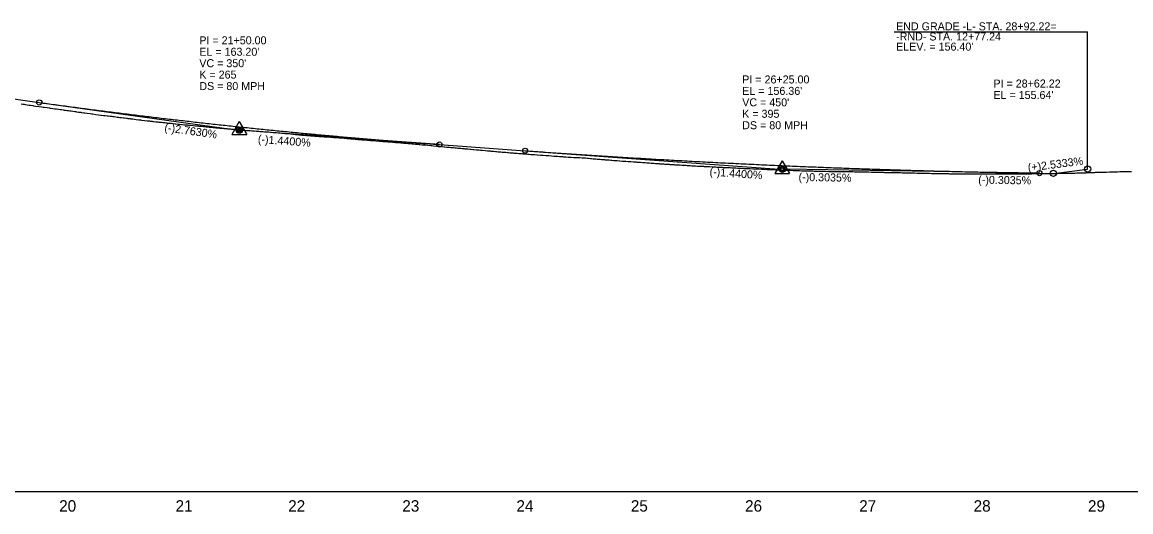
# Model space of a CAD drawing. Extents: x 1778432 to 1784301, y 601022 to 621789.
# Drawn here: x 1781103 to 1782073, y 621022 to 621450 of the extents above; entities that cross this region are included whole.
import ezdxf

# ---------------------------------------------------------------- set-up
doc = ezdxf.new("R2010")
doc.units = 0
for name, color, linetype in [('Exist Profile Cell', 7, 'Continuous'), ('Exist Vertical Profile Ground Line', 7, 'Continuous'), ('Exist Vertical Profile Horizontal Axis Label Major', 7, 'Continuous'), ('Prop PFL VPI Symbol CELL', 7, 'Continuous'), ('Prop Vertical Profile Curve Label', 7, 'Continuous'), ('Prop Vertical Profile Grade', 7, 'Continuous'), ('Prop Vertical Profile Grade Label', 7, 'Continuous'), ('Prop VPI Label', 7, 'Continuous')]:
    doc.layers.add(name, color=color, linetype=linetype)

msp = doc.modelspace()

# ---------------------------------------------------------------- linework, layer by layer
at = {"layer": 'Exist Profile Cell'}
msp.add_line((1780142.96, 621039.19), (1784155.69, 621039.19), dxfattribs=at)
at = {"layer": 'Exist Vertical Profile Ground Line'}
msp.add_lwpolyline([(1781102.23, 621378.18), (1781103.68, 621377.98), (1781104.73, 621377.81), (1781105.67, 621377.66), (1781107.23, 621377.43), (1781109.02, 621377.12), (1781109.74, 621377), (1781110.39, 621376.89), (1781112.24, 621376.6), (1781112.76, 621376.52), (1781114.75, 621376.24), (1781117.49, 621375.88), (1781119.75, 621375.55), (1781121.39, 621375.35), (1781122.26, 621375.24), (1781124.77, 621374.88), (1781126.96, 621374.56), (1781127.27, 621374.52), (1781127.62, 621374.47), (1781129.78, 621374.15), (1781131.68, 621373.87), (1781132.28, 621373.79), (1781132.96, 621373.7), (1781134.78, 621373.45), (1781136.4, 621373.22), (1781137.29, 621373.11), (1781138.78, 621372.9), (1781139.79, 621372.77), (1781140.95, 621372.61), (1781142.3, 621372.4), (1781143.5, 621372.23), (1781144.8, 621372.06), (1781145.87, 621371.91), (1781147.31, 621371.71), (1781148.93, 621371.51), (1781149.81, 621371.37), (1781150.59, 621371.26), (1781152.32, 621371.01), (1781154.25, 621370.75), (1781154.82, 621370.66), (1781156.92, 621370.35), (1781157.32, 621370.29), (1781157.69, 621370.24), (1781159.83, 621369.95), (1781162.33, 621369.63), (1781163.83, 621369.43), (1781164.84, 621369.29), (1781167.55, 621368.91), (1781169.84, 621368.64), (1781171.87, 621368.39), (1781172.35, 621368.33), (1781174.26, 621368.07), (1781174.86, 621368), (1781175.53, 621367.91), (1781177.36, 621367.69), (1781178.21, 621367.6), (1781179.86, 621367.4), (1781181.34, 621367.26), (1781182.37, 621367.14), (1781183.52, 621367), (1781184.87, 621366.81), (1781186.19, 621366.64), (1781187.37, 621366.49), (1781188.43, 621366.35), (1781189.88, 621366.18), (1781191.5, 621365.97), (1781192.38, 621365.86), (1781194.18, 621365.62), (1781194.89, 621365.52), (1781195.52, 621365.44), (1781197.39, 621365.24), (1781197.9, 621365.18), (1781199.89, 621364.92), (1781202.61, 621364.59), (1781204.99, 621364.32), (1781206.51, 621364.13), (1781207.46, 621364), (1781210.14, 621363.67), (1781212.42, 621363.41), (1781214.45, 621363.18), (1781214.93, 621363.13), (1781216.81, 621362.9), (1781217.43, 621362.83), (1781218.12, 621362.75), (1781219.93, 621362.54), (1781221.54, 621362.36), (1781222.44, 621362.27), (1781223.91, 621362.11), (1781224.95, 621362), (1781226.1, 621361.89), (1781227.44, 621361.76), (1781228.78, 621361.61), (1781229.95, 621361.48), (1781230.99, 621361.37), (1781232.45, 621361.22), (1781233.37, 621361.12), (1781234.96, 621360.98), (1781236.75, 621360.81), (1781237.46, 621360.74), (1781239.42, 621360.51), (1781239.97, 621360.46), (1781240.45, 621360.4), (1781242.47, 621360.19), (1781242.82, 621360.15), (1781244.97, 621359.94), (1781247.48, 621359.72), (1781248.64, 621359.61), (1781249.98, 621359.48), (1781252.48, 621359.26), (1781254.65, 621359.04), (1781254.99, 621359.01), (1781257.02, 621358.8), (1781257.5, 621358.75), (1781258.04, 621358.7), (1781260, 621358.51), (1781261.73, 621358.31), (1781262.5, 621358.24), (1781264.1, 621358.11), (1781265.01, 621358.02), (1781266.47, 621357.86), (1781267.52, 621357.75), (1781268.68, 621357.66), (1781270.02, 621357.55), (1781271.37, 621357.41), (1781272.52, 621357.29), (1781273.56, 621357.2), (1781275.03, 621357.07), (1781275.93, 621356.98), (1781277.54, 621356.83), (1781279.32, 621356.68), (1781280.04, 621356.62), (1781282.01, 621356.47), (1781282.54, 621356.42), (1781283.02, 621356.38), (1781285.04, 621356.2), (1781285.38, 621356.17), (1781287.75, 621355.95), (1781290.06, 621355.77), (1781291.45, 621355.66), (1781292.62, 621355.57), (1781295.3, 621355.32), (1781297.57, 621355.09), (1781299.57, 621354.95), (1781300.07, 621354.91), (1781301.94, 621354.79), (1781302.58, 621354.76), (1781304.32, 621354.61), (1781305.08, 621354.55), (1781305.93, 621354.49), (1781307.58, 621354.39), (1781308.6, 621354.31), (1781310.09, 621354.2), (1781311.28, 621354.12), (1781312.59, 621354.02), (1781313.75, 621353.92), (1781315.09, 621353.83), (1781316.13, 621353.74), (1781317.6, 621353.64), (1781318.5, 621353.56), (1781320.1, 621353.43), (1781320.86, 621353.36), (1781322.61, 621353.21), (1781323.24, 621353.15), (1781325.12, 621353), (1781327.22, 621352.83), (1781327.62, 621352.8), (1781330.12, 621352.6), (1781332.68, 621352.37), (1781333.47, 621352.3), (1781335.13, 621352.15), (1781337.63, 621351.93), (1781339.77, 621351.73), (1781340.14, 621351.69), (1781342.14, 621351.5), (1781342.65, 621351.46), (1781343.22, 621351.4), (1781345.15, 621351.21), (1781346.87, 621351.02), (1781347.65, 621350.92), (1781349.25, 621350.75), (1781350.16, 621350.64), (1781351.62, 621350.53), (1781352.66, 621350.44), (1781353.83, 621350.38), (1781355.16, 621350.26), (1781356.49, 621350.17), (1781357.67, 621350.08), (1781359.16, 621349.98), (1781360.17, 621349.9), (1781361.07, 621349.82), (1781362.68, 621349.71), (1781364.49, 621349.59), (1781365.19, 621349.54), (1781367.15, 621349.4), (1781367.68, 621349.36), (1781369.82, 621349.24), (1781370.2, 621349.22), (1781370.53, 621349.19), (1781372.7, 621349.05), (1781375.26, 621348.87), (1781376.15, 621348.82), (1781377.7, 621348.72), (1781380.46, 621348.52), (1781382.71, 621348.3), (1781384.72, 621348.13), (1781385.22, 621348.09), (1781387.08, 621347.94), (1781387.72, 621347.89), (1781389.45, 621347.74), (1781390.22, 621347.68), (1781391.09, 621347.61), (1781392.73, 621347.46), (1781394.19, 621347.33), (1781395.23, 621347.25), (1781396.55, 621347.13), (1781397.74, 621347.03), (1781399.45, 621346.91), (1781400.25, 621346.84), (1781401.29, 621346.76), (1781402.75, 621346.63), (1781403.65, 621346.55), (1781405.25, 621346.42), (1781406.01, 621346.36), (1781407.76, 621346.24), (1781408.38, 621346.19), (1781410.26, 621346.02), (1781412.39, 621345.84), (1781412.77, 621345.8), (1781415.27, 621345.6), (1781417.77, 621345.42), (1781418.51, 621345.37), (1781420.27, 621345.25), (1781422.78, 621345.04), (1781424.91, 621344.88), (1781425.28, 621344.85), (1781427.27, 621344.71), (1781427.79, 621344.68), (1781429.64, 621344.51), (1781430.3, 621344.45), (1781431.03, 621344.39), (1781432.8, 621344.25), (1781434.38, 621344.11), (1781435.3, 621344.04), (1781436.76, 621343.92), (1781437.81, 621343.83), (1781438.99, 621343.73), (1781440.31, 621343.63), (1781441.49, 621343.51), (1781442.82, 621343.4), (1781444.32, 621343.28), (1781445.32, 621343.22), (1781446.99, 621343.03), (1781447.83, 621342.94), (1781449.66, 621342.77), (1781450.33, 621342.7), (1781450.92, 621342.64), (1781452.84, 621342.46), (1781453.3, 621342.42), (1781455.34, 621342.23), (1781455.67, 621342.19), (1781457.84, 621341.99), (1781460.41, 621341.74), (1781461.52, 621341.64), (1781462.86, 621341.51), (1781465.36, 621341.29), (1781467.49, 621341.08), (1781467.86, 621341.04), (1781469.85, 621340.84), (1781470.36, 621340.78), (1781472.21, 621340.6), (1781472.87, 621340.55), (1781474.58, 621340.42), (1781475.37, 621340.35), (1781476.95, 621340.21), (1781477.88, 621340.12), (1781479.33, 621339.98), (1781480.39, 621339.89), (1781481.69, 621339.78), (1781482.89, 621339.69), (1781484.05, 621339.55), (1781485.39, 621339.43), (1781486.9, 621339.29), (1781487.89, 621339.19), (1781489.57, 621339.03), (1781490.4, 621338.96), (1781491.14, 621338.9), (1781492.91, 621338.75), (1781494.9, 621338.55), (1781495.41, 621338.51), (1781497.55, 621338.32), (1781498.02, 621338.28), (1781500.49, 621338.02), (1781502.94, 621337.81), (1781503.86, 621337.73), (1781505.48, 621337.59), (1781507.93, 621337.38), (1781510.07, 621337.18), (1781510.44, 621337.14), (1781512.44, 621336.97), (1781512.95, 621336.92), (1781514.79, 621336.74), (1781515.44, 621336.69), (1781517.16, 621336.55), (1781517.95, 621336.49), (1781519.51, 621336.35), (1781520.45, 621336.26), (1781521.88, 621336.16), (1781522.95, 621336.06), (1781523.64, 621336.02), (1781525, 621335.9), (1781525.46, 621335.84), (1781526.12, 621335.78), (1781527.52, 621335.65), (1781528.6, 621335.59), (1781530.03, 621335.47), (1781531.08, 621335.36), (1781532.56, 621335.25), (1781533.55, 621335.16), (1781535.09, 621335.05), (1781536.01, 621334.97), (1781537.63, 621334.82), (1781538.45, 621334.76), (1781540.19, 621334.62), (1781540.87, 621334.57), (1781542.79, 621334.42), (1781543.15, 621334.39), (1781545.53, 621334.22), (1781546.32, 621334.16), (1781548.05, 621334.02), (1781548.81, 621333.97), (1781550.62, 621333.83), (1781551.3, 621333.75), (1781553.43, 621333.58), (1781553.91, 621333.55), (1781556.37, 621333.36), (1781558.81, 621333.18), (1781561.26, 621333.04), (1781561.71, 621333.01), (1781563.86, 621332.9), (1781566.02, 621332.67), (1781568.21, 621332.54), (1781568.64, 621332.52), (1781570.69, 621332.37), (1781571.22, 621332.33), (1781573.18, 621332.18), (1781573.78, 621332.12), (1781575.67, 621332), (1781576.63, 621331.93), (1781577.37, 621331.88), (1781578.05, 621331.85), (1781578.66, 621331.81), (1781580.56, 621331.66), (1781581.02, 621331.62), (1781583.06, 621331.51), (1781583.38, 621331.5), (1781585.56, 621331.39), (1781588.09, 621331.28), (1781588.45, 621331.27), (1781590.64, 621331.2), (1781592.78, 621331.07), (1781593.27, 621331.04), (1781595.25, 621330.89), (1781595.85, 621330.85), (1781597.66, 621330.69), (1781598.42, 621330.64), (1781600.09, 621330.43), (1781600.98, 621330.32), (1781602.52, 621330.17), (1781603.54, 621330.09), (1781604.97, 621329.97), (1781606.09, 621329.88), (1781607.41, 621329.78), (1781608.63, 621329.67), (1781609.86, 621329.58), (1781611.17, 621329.47), (1781612.32, 621329.39), (1781613.11, 621329.35), (1781614.63, 621329.21), (1781615.62, 621329.13), (1781616.49, 621329.07), (1781618.13, 621328.96), (1781618.87, 621328.89), (1781620.63, 621328.77), (1781621.23, 621328.72), (1781623.13, 621328.58), (1781623.58, 621328.55), (1781625.63, 621328.42), (1781625.94, 621328.4), (1781628.3, 621328.19), (1781630.65, 621328.03), (1781631.04, 621328), (1781633.15, 621327.85), (1781635.65, 621327.66), (1781637.78, 621327.51), (1781638.15, 621327.47), (1781640.15, 621327.33), (1781640.66, 621327.29), (1781641.23, 621327.26), (1781643.16, 621327.1), (1781643.9, 621327.06), (1781645.67, 621326.93), (1781646.57, 621326.88), (1781648.17, 621326.76), (1781649.6, 621326.66), (1781650.68, 621326.6), (1781651.97, 621326.5), (1781653.19, 621326.42), (1781654.55, 621326.32), (1781655.69, 621326.22), (1781657.21, 621326.1), (1781658.19, 621326.02), (1781659.87, 621325.89), (1781660.69, 621325.83), (1781661.42, 621325.78), (1781663.2, 621325.67), (1781664.19, 621325.6), (1781664.87, 621325.55), (1781665.7, 621325.51), (1781666.5, 621325.46), (1781667.13, 621325.41), (1781668.21, 621325.37), (1781669.02, 621325.3), (1781669.61, 621325.26), (1781670.89, 621325.16), (1781673.25, 621325), (1781673.89, 621324.96), (1781675.52, 621324.85), (1781675.87, 621324.83), (1781677.82, 621324.74), (1781678.53, 621324.71), (1781680.18, 621324.62), (1781681.12, 621324.56), (1781682.53, 621324.48), (1781683.71, 621324.41), (1781684.93, 621324.33), (1781686.28, 621324.24), (1781687.35, 621324.17), (1781688.83, 621324.09), (1781689.78, 621324.05), (1781691.38, 621323.96), (1781692.22, 621323.91), (1781693.92, 621323.82), (1781694.67, 621323.79), (1781696.46, 621323.67), (1781697.13, 621323.63), (1781698.98, 621323.55), (1781699.59, 621323.52), (1781701.51, 621323.42), (1781702.06, 621323.39), (1781704.03, 621323.28), (1781704.53, 621323.26), (1781706.66, 621323.15), (1781707.11, 621323.12), (1781709.18, 621323.01), (1781709.59, 621322.99), (1781710.77, 621322.94), (1781711.7, 621322.88), (1781712.07, 621322.86), (1781713.28, 621322.8), (1781714.21, 621322.76), (1781714.56, 621322.74), (1781715.78, 621322.68), (1781716.73, 621322.63), (1781717.04, 621322.62), (1781717.92, 621322.6), (1781718.58, 621322.58), (1781720.17, 621322.51), (1781721.29, 621322.46), (1781722.51, 621322.39), (1781723.91, 621322.3), (1781724.88, 621322.25), (1781726.51, 621322.18), (1781727.3, 621322.14), (1781729.08, 621322.06), (1781729.98, 621322.02), (1781731.88, 621321.91), (1781732.43, 621321.87), (1781734.43, 621321.78), (1781734.9, 621321.76), (1781736.97, 621321.67), (1781737.38, 621321.64), (1781739.51, 621321.56), (1781739.85, 621321.55), (1781742.33, 621321.43), (1781744.82, 621321.33), (1781747.3, 621321.29), (1781749.79, 621321.12), (1781752.28, 621321), (1781754.77, 621320.9), (1781757.32, 621320.78), (1781758.37, 621320.75), (1781759.8, 621320.68), (1781760.12, 621320.66), (1781762.38, 621320.55), (1781764.3, 621320.48), (1781764.79, 621320.46), (1781767.31, 621320.33), (1781769.83, 621320.26), (1781772.35, 621320.16), (1781774.88, 621320.08), (1781777.42, 621319.99), (1781779.61, 621319.91), (1781779.95, 621319.9), (1781782.06, 621319.83), (1781782.5, 621319.82), (1781783.18, 621319.81), (1781785.19, 621319.73), (1781785.69, 621319.71), (1781787.61, 621319.63), (1781788.2, 621319.62), (1781790.01, 621319.57), (1781790.72, 621319.55), (1781792.39, 621319.51), (1781793.25, 621319.5), (1781794.72, 621319.47), (1781795.78, 621319.45), (1781796.99, 621319.43), (1781798.33, 621319.41), (1781799.13, 621319.39), (1781801.01, 621319.34), (1781802.85, 621319.26), (1781803.44, 621319.28), (1781805.33, 621319.22), (1781806.15, 621319.2), (1781806.54, 621319.2), (1781808.65, 621319.16), (1781809.09, 621319.15), (1781811.15, 621319.13), (1781811.63, 621319.13), (1781813.65, 621319.11), (1781814.18, 621319.1), (1781816.14, 621319.09), (1781816.73, 621319.08), (1781818.64, 621319.05), (1781819.3, 621319.04), (1781821.13, 621319), (1781821.87, 621318.99), (1781823.63, 621318.98), (1781824.46, 621318.97), (1781826.13, 621318.98), (1781827.07, 621318.96), (1781828.62, 621318.91), (1781829.69, 621318.89), (1781831.11, 621318.84), (1781832.15, 621318.82), (1781833.31, 621318.8), (1781834.51, 621318.76), (1781835.85, 621318.74), (1781836.84, 621318.72), (1781838.39, 621318.69), (1781839.14, 621318.67), (1781840.93, 621318.64), (1781841.38, 621318.64), (1781843.69, 621318.61), (1781846.02, 621318.55), (1781848.52, 621318.49), (1781848.83, 621318.48), (1781851.02, 621318.44), (1781852.54, 621318.38), (1781853.53, 621318.37), (1781854.01, 621318.35), (1781854.78, 621318.34), (1781856.04, 621318.31), (1781856.5, 621318.3), (1781857.33, 621318.28), (1781858.98, 621318.26), (1781859.88, 621318.25), (1781861.46, 621318.21), (1781862.44, 621318.2), (1781863.95, 621318.17), (1781865, 621318.15), (1781866.42, 621318.13), (1781867.57, 621318.1), (1781868.9, 621318.07), (1781870.16, 621318.04), (1781871.38, 621318), (1781872.76, 621317.97), (1781873.84, 621317.95), (1781874.17, 621317.94), (1781875.68, 621317.9), (1781876.58, 621317.87), (1781878.25, 621317.83), (1781879, 621317.81), (1781880.84, 621317.77), (1781881.39, 621317.76), (1781883.75, 621317.71), (1781886.1, 621317.66), (1781888.78, 621317.63), (1781891.1, 621317.57), (1781893.17, 621317.52), (1781893.59, 621317.51), (1781895.54, 621317.45), (1781896.11, 621317.44), (1781896.74, 621317.43), (1781898.61, 621317.37), (1781899.41, 621317.36), (1781900.73, 621317.29), (1781901.12, 621317.3), (1781902.11, 621317.26), (1781903.25, 621317.26), (1781903.62, 621317.28), (1781904.55, 621317.27), (1781905.78, 621317.24), (1781906.12, 621317.24), (1781907, 621317.21), (1781908.3, 621317.2), (1781908.62, 621317.19), (1781909.43, 621317.18), (1781910.84, 621317.16), (1781911.87, 621317.13), (1781913.38, 621317.13), (1781914.29, 621317.12), (1781915.91, 621317.12), (1781916.71, 621317.11), (1781918.69, 621317.08), (1781920.63, 621317.1), (1781921.19, 621317.09), (1781923.3, 621317.09), (1781923.68, 621317.09), (1781926.17, 621317.09), (1781928.21, 621317.08), (1781928.7, 621317.08), (1781931.16, 621317.07), (1781933.67, 621317.03), (1781933.99, 621317.03), (1781936.17, 621317.01), (1781936.66, 621317.01), (1781938.68, 621316.99), (1781939.34, 621316.99), (1781941.18, 621316.98), (1781942.83, 621316.97), (1781943.68, 621316.98), (1781945.2, 621316.96), (1781946.19, 621316.97), (1781947.3, 621316.96), (1781948.69, 621316.95), (1781949.97, 621316.96), (1781951.2, 621316.96), (1781952.63, 621316.97), (1781953.7, 621316.95), (1781954.64, 621316.95), (1781956.21, 621316.95), (1781956.54, 621316.94), (1781958.38, 621316.94), (1781959, 621316.93), (1781961.45, 621316.92), (1781963.91, 621316.93), (1781966.35, 621316.95), (1781968.78, 621316.96), (1781970.52, 621316.97), (1781971.28, 621316.97), (1781973.94, 621316.99), (1781976.24, 621317), (1781978.3, 621317.04), (1781978.74, 621317.06), (1781980.67, 621317.08), (1781981.26, 621317.09), (1781983.04, 621317.11), (1781983.76, 621317.12), (1781985.39, 621317.11), (1781986.26, 621317.11), (1781987.23, 621317.13), (1781988.76, 621317.14), (1781989.89, 621317.16), (1781991.27, 621317.16), (1781992.49, 621317.17), (1781993.78, 621317.19), (1781995.22, 621317.25), (1781996.27, 621317.26), (1781997.21, 621317.28), (1781998.78, 621317.29), (1781999.58, 621317.29), (1782001.28, 621317.31), (1782001.94, 621317.31), (1782003.79, 621317.35), (1782004.31, 621317.35), (1782006.29, 621317.38), (1782006.67, 621317.38), (1782008.8, 621317.41), (1782011.3, 621317.43), (1782013.32, 621317.47), (1782013.83, 621317.47), (1782016.51, 621317.52), (1782018.82, 621317.55), (1782019.16, 621317.55), (1782021.32, 621317.58), (1782021.83, 621317.59), (1782023.83, 621317.65), (1782025.59, 621317.73), (1782026.33, 621317.76), (1782027.96, 621317.81), (1782028.83, 621317.83), (1782030.32, 621317.88), (1782031.33, 621317.92), (1782032.68, 621317.96), (1782033.84, 621317.99), (1782035.05, 621318.05), (1782036.35, 621318.09), (1782037.8, 621318.14), (1782038.85, 621318.16), (1782039.77, 621318.19), (1782041.35, 621318.25), (1782042.15, 621318.29), (1782043.87, 621318.33), (1782044.52, 621318.36), (1782046.36, 621318.4), (1782046.88, 621318.41), (1782048.87, 621318.49), (1782049.24, 621318.5), (1782051.61, 621318.57), (1782054.26, 621318.64), (1782055.68, 621318.68), (1782056.42, 621318.69), (1782057.48, 621318.72), (1782059.09, 621318.76), (1782060.7, 621318.8), (1782061.39, 621318.81), (1782063.46, 621318.89), (1782063.92, 621318.9), (1782065.85, 621318.93), (1782066.4, 621318.94), (1782067.13, 621318.95), (1782068.9, 621318.98), (1782069.64, 621318.99), (1782070.35, 621319), (1782071.4, 621319.03), (1782072.26, 621319.04), (1782073.57, 621319.07)], dxfattribs=at)
at = {"layer": 'Prop PFL VPI Symbol CELL'}
for p, q in [((1781292.95, 621362.67), (1781286.5, 621351.47)), ((1781292.95, 621362.67), (1781299.45, 621351.47)), ((1781286.5, 621351.47), (1781299.45, 621351.47)), ((1781767.95, 621328.46), (1781761.5, 621317.26)), ((1781767.95, 621328.46), (1781774.45, 621317.26)), ((1781761.5, 621317.26), (1781774.45, 621317.26))]:
    msp.add_line(p, q, dxfattribs=at)
for centre, radius in [((1781292.96, 621355.19), 1.75), ((1781292.96, 621355.19), 1.2), ((1781767.96, 621320.98), 1.75), ((1781767.96, 621320.98), 1.2)]:
    msp.add_circle(centre, radius, dxfattribs=at)
at = {"layer": 'Prop Vertical Profile Curve Label'}
for centre in [(1781117.96, 621379.37), (1781467.96, 621342.59), (1781542.96, 621337.18), (1781992.96, 621317.58)]:
    msp.add_circle(centre, 2.25, dxfattribs=at)
at = {"layer": 'Prop Vertical Profile Grade'}
for p, q in [((1780952.39, 621402.24), (1781117.96, 621379.37)), ((1781467.96, 621342.59), (1781542.96, 621337.18)), ((1781992.96, 621317.58), (1782005.18, 621317.39)), ((1782005.18, 621317.39), (1782035.18, 621321.17))]:
    msp.add_line(p, q, dxfattribs=at)
for points in [[(1781117.96, 621379.37), (1781124.96, 621378.41), (1781131.96, 621377.45), (1781138.96, 621376.51), (1781145.96, 621375.57), (1781152.96, 621374.65), (1781159.96, 621373.73), (1781166.96, 621372.83), (1781173.96, 621371.93), (1781180.96, 621371.04), (1781187.96, 621370.16), (1781194.96, 621369.29), (1781201.96, 621368.43), (1781208.96, 621367.58), (1781215.96, 621366.74), (1781222.96, 621365.9), (1781229.96, 621365.08), (1781236.96, 621364.27), (1781243.96, 621363.46), (1781250.96, 621362.67), (1781257.96, 621361.88), (1781264.96, 621361.1), (1781271.96, 621360.33), (1781278.96, 621359.57), (1781285.96, 621358.82), (1781292.96, 621358.08), (1781299.96, 621357.35), (1781306.96, 621356.63), (1781313.96, 621355.92), (1781320.96, 621355.22), (1781327.96, 621354.52), (1781334.96, 621353.84), (1781341.96, 621353.16), (1781348.96, 621352.5), (1781355.96, 621351.84), (1781362.96, 621351.19), (1781369.96, 621350.55), (1781376.96, 621349.92), (1781383.96, 621349.3), (1781390.96, 621348.69), (1781397.96, 621348.09), (1781404.96, 621347.5), (1781411.96, 621346.92), (1781418.96, 621346.34), (1781425.96, 621345.78), (1781432.96, 621345.22), (1781439.96, 621344.68), (1781446.96, 621344.14), (1781453.96, 621343.61), (1781460.96, 621343.1), (1781467.96, 621342.59)], [(1781542.96, 621337.18), (1781551.96, 621336.54), (1781560.96, 621335.91), (1781569.96, 621335.29), (1781578.96, 621334.67), (1781587.96, 621334.07), (1781596.96, 621333.48), (1781605.96, 621332.9), (1781614.96, 621332.33), (1781623.96, 621331.77), (1781632.96, 621331.21), (1781641.96, 621330.67), (1781650.96, 621330.14), (1781659.96, 621329.62), (1781668.96, 621329.11), (1781677.96, 621328.61), (1781686.96, 621328.12), (1781695.96, 621327.64), (1781704.96, 621327.18), (1781713.96, 621326.72), (1781722.96, 621326.27), (1781731.96, 621325.83), (1781740.96, 621325.4), (1781749.96, 621324.98), (1781758.96, 621324.58), (1781767.96, 621324.18), (1781776.96, 621323.79), (1781785.96, 621323.42), (1781794.96, 621323.05), (1781803.96, 621322.69), (1781812.96, 621322.35), (1781821.96, 621322.01), (1781830.96, 621321.69), (1781839.96, 621321.37), (1781848.96, 621321.07), (1781857.96, 621320.77), (1781866.96, 621320.49), (1781875.96, 621320.21), (1781884.96, 621319.95), (1781893.96, 621319.69), (1781902.96, 621319.45), (1781911.96, 621319.22), (1781920.96, 621318.99), (1781929.96, 621318.78), (1781938.96, 621318.58), (1781947.96, 621318.39), (1781956.96, 621318.2), (1781965.96, 621318.03), (1781974.96, 621317.87), (1781983.96, 621317.72), (1781992.96, 621317.58)]]:
    msp.add_spline(points, degree=3, dxfattribs=at)
at = {"layer": 'Prop VPI Label'}
for p, q in [((1781865.97, 621441.17), (1782035.18, 621441.17)), ((1782035.18, 621321.17), (1782035.18, 621441.17)), ((1781117.96, 621379.37), (1781290.24, 621355.57)), ((1781467.96, 621342.59), (1781295.7, 621354.99)), ((1781542.96, 621337.18), (1781765.22, 621321.18)), ((1781992.96, 621317.58), (1781770.71, 621320.94))]:
    msp.add_line(p, q, dxfattribs=at)
for centre in [(1781292.96, 621355.19), (1781767.96, 621320.98), (1782035.18, 621321.17), (1782005.18, 621317.39)]:
    msp.add_circle(centre, 2.75, dxfattribs=at)

# ---------------------------------------------------------------- texts
at = {"layer": 'Exist Vertical Profile Horizontal Axis Label Major'}
for s, p in [('20', (1781135.35, 621021.69)), ('21', (1781237.19, 621021.69)), ('22', (1781335.73, 621021.69)), ('23', (1781435.57, 621021.69)), ('24', (1781535.41, 621021.69)), ('25', (1781635.5, 621021.69)), ('26', (1781735.44, 621021.69)), ('27', (1781835.3, 621021.69)), ('28', (1781935.43, 621021.69)), ('29', (1782035.47, 621021.69))]:
    msp.add_text(s, height=10, dxfattribs=at).set_placement(p)
at = {"layer": 'Prop Vertical Profile Curve Label'}
for s, p in [("VC = 350'", (1781257.96, 621410.19)), ('K = 265', (1781257.96, 621400.19)), ('DS = 80 MPH', (1781257.96, 621390.19)), ("VC = 450'", (1781732.96, 621375.98)), ('K = 395', (1781732.96, 621365.98)), ('DS = 80 MPH', (1781732.96, 621355.98))]:
    msp.add_text(s, height=7, dxfattribs=at).set_placement(p)
at = {"layer": 'Prop Vertical Profile Grade Label'}
for s, rotation, p in [('(-)2.7630%', 352.13433, (1781227.13, 621354.19)), ('(-)1.4400%', 355.88023, (1781309, 621344.01)), ('(+)2.5333%', 7.1786, (1781983.27, 621318.9)), ('(-)1.4400%', 355.88023, (1781704.2, 621315.54)), ('(-)0.3035%', 359.13375, (1781782.18, 621310.76)), ('(-)0.3035%', 359.13375, (1781939.41, 621308.39))]:
    msp.add_text(s, height=7, rotation=rotation, dxfattribs=at).set_placement(p)
at = {"layer": 'Prop VPI Label'}
for s, p in [('END GRADE -L- STA. 28+92.22=', (1781867.57, 621442.42)), ('-RND- STA. 12+77.24', (1781867.57, 621433.55)), ('PI = 21+50.00', (1781257.96, 621430.19)), ("ELEV. = 156.40'", (1781867.57, 621424.67)), ("EL = 163.20'", (1781257.96, 621420.19)), ('PI = 26+25.00', (1781732.96, 621395.98)), ("EL = 156.36'", (1781732.96, 621385.98)), ('PI = 28+62.22', (1781952.74, 621392.42)), ("EL = 155.64'", (1781952.74, 621382.42))]:
    msp.add_text(s, height=7, dxfattribs=at).set_placement(p)

doc.saveas('drawing.dxf')
